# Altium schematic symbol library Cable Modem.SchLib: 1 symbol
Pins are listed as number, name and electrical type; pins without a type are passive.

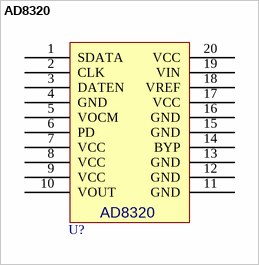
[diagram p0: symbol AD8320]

## AD8320
designator U?
pins: 1 SDATA, 2 CLK, 3 DATEN, 4 GND (power), 5 VOCM, 6 PD, 7 VCC (power), 8 VCC (power), 9 VCC (power), 10 VOUT, 11 GND (power), 12 GND (power), 13 GND (power), 14 BYP, 15 GND (power), 16 GND (power), 17 VCC (power), 18 VREF, 19 VIN, 20 VCC (power)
